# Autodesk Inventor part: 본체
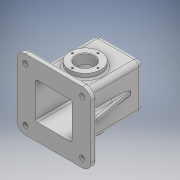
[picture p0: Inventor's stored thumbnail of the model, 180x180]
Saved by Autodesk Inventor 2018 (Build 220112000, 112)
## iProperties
Created: 2022-11
Part Number: 본체
Material: 일반
Document SubType Name: Modeling
Designer: home
Density: 1 g/cm^3
Appearance: 기본값
Author: home
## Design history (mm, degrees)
sketch "스케치1"
  geometry: L1 (-50, 62)-(50, 62); L2 (65, 47)-(65, -47); L3 (50, -62)-(-50, -62); L4 (-65, -47)-(-65, 47); L5 (-65, 62)-(65, -62); L6 (65, 62)-(-65, -62); A1 r 15 centre (50, 47) between (65, 47) and (50, 62); A2 r 15 centre (50, -47) between (50, -62) and (65, -47); A3 r 15 centre (-50, 47) between (-50, 62) and (-65, 47); A4 r 15 centre (-50, -47) between (-65, -47) and (-50, -62); 1 further point
  constraints: 12 end point, 8 point on circle, 8 point on line, 8 tangent, 4 centre point, 3 equal radius, 2 midpoint, 2 parallel, 1 horizontal, 1 perpendicular
  dimensions: "d2" = 15 radius of A1; "d3" = 46.3532 deg angle of L5 L2; "d4" = 130 distance between parallel lines of L2 L4
extrude "돌출1" new body sketch "스케치1" distance "d5" = 10; taper "d6" = 0 deg
sketch "스케치2"
  geometry: L1 (40, -40)-(-40, -40); L2 (-40, -40)-(-40, 40); L3 (-40, 40)-(40, 40); L4 (40, 40)-(40, -40); L5 (40, -40)-(-40, 40); L6 (-40, -40)-(40, 40); 1 further point
  constraints: 12 end point, 2 midpoint, 2 parallel, 1 horizontal, 1 perpendicular
  dimensions: "d7" = 80 distance of L2.end L3.end; "d8" = 80 distance of L1.end L2.end
extrude "돌출2" join sketch "스케치2" distance "d9" = 107; taper "d10" = 0 deg
node "작업 평면1"
sketch "스케치3"
  geometry: L1 (40, -10)-(40, 45); C1 r 27.5 at (40, 45)
  constraints: 2 end point, 1 centre point, 1 coincident, 1 vertical
  dimensions: "d12" = 55 distance of L1.start L1.end; "d13" = 55 diameter of C1
extrude "돌출3" join sketch "스케치3" stored distance "d14" = 107; taper "d15" = 0 deg
sketch "스케치4"
  geometry: L1 (55, 10)-(38.753, 102.144); L2 (-55, 10)-(-39.372, 98.633); L3 (-55, 10)-(55, 10); 1 further point
  constraints: 6 end point, 1 horizontal
  dimensions: "d22" = 90 distance of L2.start L2.end; "d23" = 110 distance of L1.start L2.start; "d24" = 80 deg angle of L1 L3; "d25" = 20 deg angle of L1 L2; "d26" = 55.90091 distance from line of point (0, 0) L1; "d27" = 10 distance from line of point (0, 0) L3; "d28" = 92.14403 distance from line of L1.end L3
feature "리브1" sketch "스케치4" dims "d29" = 1, "d30" = 10, "d31" = 0, "d32" = 0, "d33" = 1, "d34" = 1
sketch "스케치5"
  geometry: L1 (-32, -32)-(32, -32); L2 (32, -32)-(32, 32); L3 (32, 32)-(-32, 32); L4 (-32, 32)-(-32, -32); L5 (-32, -32)-(32, 32); L6 (32, -32)-(-32, 32); 1 further point
  constraints: 12 end point, 2 midpoint, 2 parallel, 1 horizontal, 1 perpendicular
  dimensions: "d35" = 64 distance of L3.end L2.end; "d36" = 64 distance of L2.end L1.end
extrude "돌출4" cut sketch "스케치5" distance "d37" = 109; taper "d38" = 0 deg
sketch "스케치6"
  geometry: C1 r 20 at (0, 0); 1 further point
  constraints: 1 centre point, 1 coincident
  dimensions: "d39" = 40 diameter of C1
extrude "돌출5" join sketch "스케치6" distance "d40" = 10; taper "d41" = -10 deg
hole "구멍1" diameter "d44" = 32; stored, may be unused: countersink angle "d48" = 90 deg, drill point angle "d50" = 118 deg; dims "d42" = 10, "d43" = 10, "d45" = 6, "d46" = 4, "d47" = 2, "d49" = 8
sketch "스케치7"
  geometry: A1 r 22.5 centre (0, 0) between (0, 22.5) and (22.5, 0); 3 further points
  constraints: 4 point on circle, 1 centre point
  dimensions: "d51" = 45 diameter of A1; "d52" = 59.42432 distance of point (0, -55) A1.end; "d53" = 77.5 distance of point (0, -55) A1.start; "d54" = 32.5 distance of point (0, -55) point (0, -22.5); "d55" = 59.42432 distance of point (0, -55) point (-22.5, 0); "d56" = 55 distance of A1.centre point (0, -55)
hole "구멍2" sketch "스케치7" at (0, 22.5), (22.5, 0), (-22.5, 0), (0, -22.5) diameter "d57" = 3.242; stored, may be unused: countersink angle "d61" = 90 deg, drill point angle "d63" = 118 deg; dims "d58" = 8, "d59" = 4, "d60" = 2, "d62" = 10
hole "구멍3" diameter "d66" = 21; stored, may be unused: countersink angle "d70" = 90 deg, drill point angle "d72" = 118 deg; dims "d64" = 10, "d65" = 10, "d67" = 8, "d68" = 28, "d69" = 4, "d71" = 10
sketch "스케치8"
  geometry: A1 r 15 centre (-50, -47) between (-65, -47) and (-50, -62) reference; A2 r 15 centre (-50, 47) between (-50, 62) and (-65, 47) reference; A3 r 15 centre (50, -47) between (50, -62) and (65, -47) reference; A4 r 15 centre (50, 47) between (65, 47) and (50, 62) reference; 5 further points
  constraints: 4 coincident
hole "구멍4" sketch "스케치8" at (-50, -47), (-50, 47), (50, -47), (50, 47) diameter "d73" = 9; stored, may be unused: countersink angle "d77" = 90 deg, drill point angle "d79" = 118 deg; dims "d74" = 8, "d75" = 28, "d76" = 4, "d78" = 10
fillet "모깎기1" dims "d80" = 8, "d84" = 3
chamfer "모따기1" distance "d81" = 1; stored, may be unused: second distance "d82" = 2, angle "d83" = 45 deg
sketch "스케치9"
  geometry: L1 (72, -96)-(72, 0) reference; L2 (13.763, 18)-(50.237, 18) reference; 2 further points
  constraints: 1 other
  dimensions: "d85" = 40 distance from line of point (32, -7) L1; "d86" = 25 distance from line of point (32, -7) L2
feature "엠보싱1" sketch "스케치9" dims "d7" = 80, "d8" = 80, "d87" = 0.5, "d88" = 0
node "솔리드1"
mirror "미러1"
mirror "미러2"
other parameters: "d11" = 9
